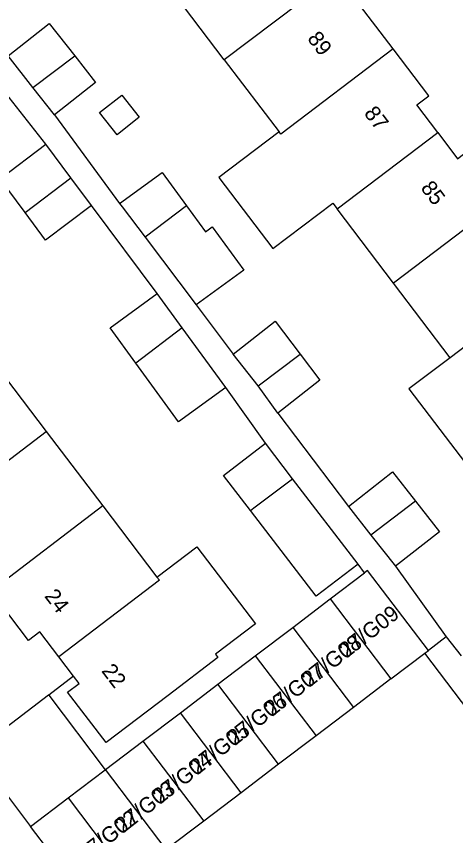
# Model space of a CAD drawing. Extents: x 160037 to 160839, y 385326 to 386441.
# Drawn here: x 160464.3 to 160492.5, y 385654.4 to 385707 of the extents above; entities that cross this region are included whole.
import ezdxf

# ---------------------------------------------------------------- set-up
doc = ezdxf.new("R2010")
doc.units = 0
for name, color, linetype in [('IMGEO_Groenvoorziening', 7, 'Continuous'), ('IMGEO_Pand', 7, 'Continuous'), ('IMGEO_Pand_nummerreeks', 7, 'Continuous'), ('IMGEO_Rijbaan_lokaal_open', 7, 'Continuous'), ('IMGEO_Voetpad_open', 7, 'Continuous')]:
    doc.layers.add(name, color=color, linetype=linetype)

msp = doc.modelspace()

# ---------------------------------------------------------------- linework, layer by layer
at = {"layer": 'IMGEO_Groenvoorziening'}
msp.add_lwpolyline([(160466.409, 385663.403), (160470.043, 385658.613)], dxfattribs=at)
at = {"layer": 'IMGEO_Pand'}
for points in [[(160477.68, 385704.185), (160474.055, 385708.967)], [(160484.177, 385709.11), (160477.68, 385704.185)], [(160488.523, 385704.877), (160486.086, 385708.092), (160485.364, 385707.545), (160484.177, 385709.11)], [(160463.8, 385704.437), (160466.439, 385706.513), (160468.076, 385704.433)], [(160488.523, 385704.877), (160481.305, 385699.404), (160481.196, 385699.548)], [(160491.382, 385699.514), (160490.042, 385701.282), (160490.808, 385701.863), (160488.523, 385704.877)], [(160465.399, 385702.404), (160463.8, 385704.437)], [(160465.399, 385702.404), (160468.076, 385704.433)], [(160468.076, 385704.433), (160469.419, 385702.727), (160466.78, 385700.65)], [(160477.68, 385704.185), (160481.196, 385699.548)], [(160466.78, 385700.65), (160465.399, 385702.404)], [(160470.798, 385699.372), (160469.674, 385700.799), (160471.101, 385701.922), (160472.225, 385700.495), (160470.798, 385699.372)], [(160481.196, 385699.548), (160477.338, 385696.623), (160480.797, 385692.062), (160484.654, 385694.987), (160484.93, 385694.623)], [(160484.93, 385694.623), (160491.382, 385699.514)], [(160491.382, 385699.514), (160492.656, 385697.833), (160493.453, 385698.437), (160495.803, 385695.337)], [(160464.89, 385694.374), (160463.265, 385696.538), (160466.219, 385698.757)], [(160467.829, 385696.613), (160466.219, 385698.757)], [(160470.963, 385694.959), (160473.686, 385696.95), (160475.253, 385694.807)], [(160464.89, 385694.374), (160467.829, 385696.613)], [(160469.166, 385694.833), (160467.829, 385696.613)], [(160495.803, 385695.337), (160488.554, 385689.841)], [(160469.166, 385694.833), (160466.212, 385692.614), (160464.89, 385694.374)], [(160470.963, 385694.959), (160471.13, 385694.738), (160472.594, 385692.799)], [(160475.253, 385694.807), (160472.594, 385692.799)], [(160475.253, 385694.807), (160476.467, 385693.148), (160476.894, 385693.461), (160478.931, 385690.676), (160475.882, 385688.446)], [(160488.554, 385689.841), (160484.93, 385694.623)], [(160472.594, 385692.799), (160475.882, 385688.446)], [(160498.687, 385689.994), (160492.179, 385685.06)], [(160492.179, 385685.06), (160488.554, 385689.841)], [(160472.006, 385684.706), (160470.349, 385686.976), (160473.372, 385689.183)], [(160474.985, 385686.973), (160473.372, 385689.183)], [(160478.261, 385685.295), (160480.944, 385687.407), (160482.546, 385685.286)], [(160474.985, 385686.973), (160472.006, 385684.706)], [(160477.773, 385683.154), (160474.985, 385686.973)], [(160479.863, 385683.251), (160478.261, 385685.295)], [(160479.863, 385683.251), (160482.546, 385685.286)], [(160482.546, 385685.286), (160483.809, 385683.614), (160481.126, 385681.503)], [(160462.612, 385685.096), (160466.245, 385680.321)], [(160492.179, 385685.06), (160489.54, 385683.06), (160493.165, 385678.279), (160495.804, 385680.279)], [(160477.773, 385683.154), (160474.75, 385680.947), (160472.006, 385684.706)], [(160481.126, 385681.503), (160479.863, 385683.251)], [(160459.79, 385675.408), (160466.245, 385680.321)], [(160466.245, 385680.321), (160469.877, 385675.548)], [(160479.362, 385675.241), (160477.629, 385677.496), (160480.319, 385679.563)], [(160482.068, 385677.286), (160480.319, 385679.563)], [(160485.657, 385675.502), (160488.481, 385677.724), (160489.958, 385675.847)], [(160479.362, 385675.241), (160479.588, 385675.413), (160482.068, 385677.286)], [(160486.273, 385671.813), (160482.068, 385677.286)], [(160489.958, 385675.847), (160487.094, 385673.676)], [(160489.958, 385675.847), (160491.498, 385673.89), (160488.674, 385671.668)], [(160469.877, 385675.548), (160462.7, 385670.081)], [(160469.877, 385675.548), (160473.355, 385670.978)], [(160485.657, 385675.502), (160487.094, 385673.676)], [(160486.273, 385671.813), (160483.583, 385669.747), (160479.362, 385675.241)], [(160487.094, 385673.676), (160488.674, 385671.668)], [(160473.355, 385670.978), (160475.919, 385672.929), (160479.68, 385667.986), (160477.115, 385666.035), (160477.277, 385665.823), (160474.07, 385663.383), (160470.09, 385660.355), (160467.622, 385663.599), (160468.355, 385664.156), (160468.003, 385664.619)], [(160484.476, 385669.574), (160486.694, 385671.259)], [(160490.782, 385666.261), (160486.88, 385671.4), (160486.694, 385671.259)], [(160473.355, 385670.978), (160473.512, 385670.772), (160467.059, 385665.86)], [(160467.059, 385665.86), (160465.841, 385667.46), (160465.115, 385666.908), (160462.7, 385670.081)], [(160482.072, 385667.749), (160484.476, 385669.574)], [(160484.476, 385669.574), (160488.378, 385664.436)], [(160479.669, 385665.924), (160482.072, 385667.749)], [(160482.072, 385667.749), (160485.975, 385662.61)], [(160468.003, 385664.619), (160467.059, 385665.86)], [(160477.265, 385664.098), (160479.669, 385665.924)], [(160479.669, 385665.924), (160483.571, 385660.785)], [(160488.378, 385664.436), (160490.563, 385666.095)], [(160490.563, 385666.095), (160490.782, 385666.261)], [(160488.378, 385664.436), (160485.975, 385662.61)], [(160474.862, 385662.273), (160477.265, 385664.098)], [(160481.168, 385658.96), (160477.265, 385664.098)], [(160472.458, 385660.448), (160474.862, 385662.273)], [(160478.764, 385657.134), (160474.862, 385662.273)], [(160485.975, 385662.61), (160483.571, 385660.785)], [(160483.571, 385660.785), (160481.168, 385658.96)], [(160470.055, 385658.622), (160472.458, 385660.448)], [(160472.458, 385660.448), (160476.361, 385655.309)], [(160467.651, 385656.797), (160470.043, 385658.613)], [(160470.043, 385658.613), (160470.055, 385658.622)], [(160473.957, 385653.484), (160470.055, 385658.622)], [(160481.168, 385658.96), (160478.764, 385657.134)], [(160478.764, 385657.134), (160476.361, 385655.309)], [(160465.248, 385654.972), (160467.651, 385656.797)], [(160467.651, 385656.797), (160471.554, 385651.658)], [(160476.361, 385655.309), (160473.957, 385653.484)], [(160469.15, 385649.833), (160465.248, 385654.972)]]:
    msp.add_lwpolyline(points, dxfattribs=at)
at = {"layer": 'IMGEO_Rijbaan_lokaal_open'}
msp.add_lwpolyline([(160513.227, 385636.408), (160497.09, 385657.497), (160490.563, 385666.095)], dxfattribs=at)
at = {"layer": 'IMGEO_Voetpad_open'}
for points in [[(160466.219, 385698.757), (160456.543, 385711.069)], [(160466.78, 385700.65), (160470.963, 385694.959)], [(160473.372, 385689.183), (160469.166, 385694.833)], [(160475.882, 385688.446), (160478.261, 385685.295)], [(160480.319, 385679.563), (160477.773, 385683.154)], [(160481.126, 385681.503), (160485.657, 385675.502)], [(160486.694, 385671.259), (160486.273, 385671.813)], [(160488.674, 385671.668), (160491.934, 385667.136)], [(160491.934, 385667.136), (160490.782, 385666.261)], [(160491.934, 385667.136), (160492.888, 385665.924)], [(160468.003, 385664.619), (160466.409, 385663.403)], [(160466.409, 385663.403), (160466.394, 385663.392), (160461.618, 385659.753)], [(160461.618, 385659.753), (160465.248, 385654.972)]]:
    msp.add_lwpolyline(points, dxfattribs=at)

# ---------------------------------------------------------------- texts
at = {"layer": 'IMGEO_Pand_nummerreeks'}
for s, rotation, p in [('89', 307.1962, (160482.97, 385705.534)), ('87', 307.1962, (160486.61, 385700.738)), ('85', 307.1959, (160490.25, 385695.941)), ('24', 307.3394, (160466.095, 385669.747)), ('27/G09', 38.0444, (160485.548, 385665.747)), ('27/G08', 38.047, (160483.157, 385663.876)), ('22', 307.3394, (160469.758, 385664.945)), ('27/G07', 38.047, (160480.759, 385661.999)), ('27/G06', 38.047, (160478.363, 385660.124)), ('27/G05', 38.047, (160475.967, 385658.249)), ('27/G04', 38.047, (160473.571, 385656.374)), ('27/G03', 38.047, (160471.175, 385654.499)), ('27/G02', 38.0444, (160468.775, 385652.621))]:
    msp.add_text(s, height=1, rotation=rotation, dxfattribs=at).set_placement(p)

doc.saveas('drawing.dxf')
